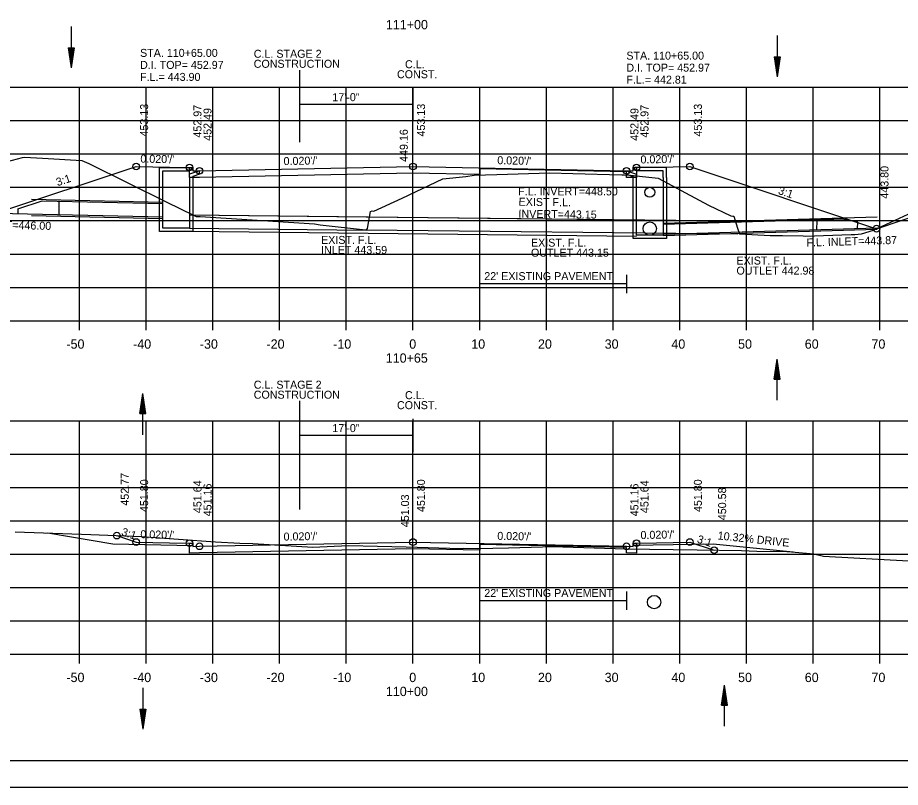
# Model space of a CAD drawing. Extents: x 1538688 to 1540766, y 656250 to 671912.
# Drawn here: x 1538798.9 to 1538931.2, y 657831.3 to 657946.7 of the extents above; entities that cross this region are included whole.
import ezdxf

# ---------------------------------------------------------------- set-up
doc = ezdxf.new("R2010")
doc.units = 0
for name, color, linetype in [('15', 7, 'Continuous'), ('16', 7, 'Continuous'), ('18', 7, 'Continuous'), ('20', 7, 'Continuous'), ('22', 7, 'Continuous'), ('26', 7, 'Continuous'), ('39', 7, 'Continuous'), ('40', 7, 'Continuous'), ('41', 7, 'Continuous'), ('42', 7, 'Continuous'), ('7', 7, 'Continuous'), ('Borings', 7, 'Continuous'), ('Default', 7, 'Continuous'), ('Horizontal Alignment', 7, 'Continuous'), ('RipRap', 7, 'Continuous'), ('Wall Heights', 7, 'Continuous')]:
    doc.layers.add(name, color=color, linetype=linetype)

msp = doc.modelspace()

# ---------------------------------------------------------------- linework, layer by layer
at = {"layer": '15'}
for p, q in [((1538806.47, 657942.19), (1538806.92, 657939.19)), ((1538806.47, 657942.19), (1538807.37, 657942.19)), ((1538806.55, 657942.19), (1538806.92, 657939.69)), ((1538806.62, 657942.19), (1538806.92, 657940.21)), ((1538806.7, 657942.19), (1538806.92, 657940.71)), ((1538806.78, 657942.19), (1538806.92, 657941.22)), ((1538806.85, 657942.19), (1538806.92, 657941.72)), ((1538807.37, 657942.19), (1538806.92, 657939.19)), ((1538807.07, 657942.19), (1538806.92, 657941.22)), ((1538807.22, 657942.19), (1538806.92, 657940.21)), ((1538807.3, 657942.19), (1538806.92, 657939.69)), ((1538807.14, 657942.19), (1538806.92, 657940.71)), ((1538806.99, 657942.19), (1538806.92, 657941.72)), ((1538912.35, 657940.82), (1538912.8, 657937.82)), ((1538912.35, 657940.82), (1538913.25, 657940.82)), ((1538912.43, 657940.82), (1538912.8, 657938.32)), ((1538912.5, 657940.82), (1538912.8, 657938.84)), ((1538912.58, 657940.82), (1538912.8, 657939.34)), ((1538912.66, 657940.82), (1538912.8, 657939.85)), ((1538912.73, 657940.82), (1538912.8, 657940.35)), ((1538913.25, 657940.82), (1538912.8, 657937.82)), ((1538912.95, 657940.82), (1538912.8, 657939.85)), ((1538913.1, 657940.82), (1538912.8, 657938.84)), ((1538913.18, 657940.82), (1538912.8, 657938.32)), ((1538913.03, 657940.82), (1538912.8, 657939.34)), ((1538912.87, 657940.82), (1538912.8, 657940.35)), ((1538912.35, 657892.5), (1538912.8, 657895.5)), ((1538912.43, 657892.5), (1538912.8, 657895)), ((1538912.5, 657892.5), (1538912.8, 657894.48)), ((1538913.25, 657892.5), (1538912.8, 657895.5)), ((1538913.18, 657892.5), (1538912.8, 657895)), ((1538913.1, 657892.5), (1538912.8, 657894.48)), ((1538912.58, 657892.5), (1538912.8, 657893.98)), ((1538912.66, 657892.5), (1538912.8, 657893.48)), ((1538912.73, 657892.5), (1538912.8, 657892.97)), ((1538913.03, 657892.5), (1538912.8, 657893.98)), ((1538912.95, 657892.5), (1538912.8, 657893.48)), ((1538912.87, 657892.5), (1538912.8, 657892.97)), ((1538912.35, 657892.5), (1538913.25, 657892.5)), ((1538817.23, 657887.33), (1538817.68, 657890.33)), ((1538818.13, 657887.33), (1538817.68, 657890.33)), ((1538817.3, 657887.33), (1538817.68, 657889.83)), ((1538817.38, 657887.33), (1538817.68, 657889.31)), ((1538818.05, 657887.33), (1538817.68, 657889.83)), ((1538817.98, 657887.33), (1538817.68, 657889.31)), ((1538817.45, 657887.33), (1538817.68, 657888.81)), ((1538817.53, 657887.33), (1538817.68, 657888.3)), ((1538817.61, 657887.33), (1538817.68, 657887.8)), ((1538817.9, 657887.33), (1538817.68, 657888.81)), ((1538817.83, 657887.33), (1538817.68, 657888.3)), ((1538817.75, 657887.33), (1538817.68, 657887.8)), ((1538817.23, 657887.33), (1538818.13, 657887.33)), ((1538904.41, 657843.61), (1538904.86, 657846.61)), ((1538905.31, 657843.61), (1538904.86, 657846.61)), ((1538904.49, 657843.61), (1538904.86, 657846.11)), ((1538904.56, 657843.61), (1538904.86, 657845.59)), ((1538905.24, 657843.61), (1538904.86, 657846.11)), ((1538905.16, 657843.61), (1538904.86, 657845.59)), ((1538904.64, 657843.61), (1538904.86, 657845.09)), ((1538904.71, 657843.61), (1538904.86, 657844.59)), ((1538904.79, 657843.61), (1538904.86, 657844.08)), ((1538905.08, 657843.61), (1538904.86, 657845.09)), ((1538905.01, 657843.61), (1538904.86, 657844.59)), ((1538904.93, 657843.61), (1538904.86, 657844.08)), ((1538817.23, 657842.99), (1538817.68, 657839.99)), ((1538817.23, 657842.99), (1538818.13, 657842.99)), ((1538817.3, 657842.99), (1538817.68, 657840.5)), ((1538817.38, 657842.99), (1538817.68, 657841.01)), ((1538817.45, 657842.99), (1538817.68, 657841.51)), ((1538817.53, 657842.99), (1538817.68, 657842.02)), ((1538817.61, 657842.99), (1538817.68, 657842.52)), ((1538818.13, 657842.99), (1538817.68, 657839.99)), ((1538817.83, 657842.99), (1538817.68, 657842.02)), ((1538817.98, 657842.99), (1538817.68, 657841.01)), ((1538818.05, 657842.99), (1538817.68, 657840.5)), ((1538817.9, 657842.99), (1538817.68, 657841.51)), ((1538817.75, 657842.99), (1538817.68, 657842.52)), ((1538904.41, 657843.61), (1538905.31, 657843.61))]:
    msp.add_line(p, q, dxfattribs=at)
at = {"layer": '16'}
for p, q in [((1538803.43, 657869.41), (1538813.18, 657867.79)), ((1538813.18, 657867.79), (1538825.18, 657867.55)), ((1538891.18, 657867.56), (1538903.18, 657867.8)), ((1538903.18, 657867.8), (1538915.19, 657866.56))]:
    msp.add_line(p, q, dxfattribs=at)
at = {"layer": '18'}
for points in [[(1538789.07, 657922.91), (1538799.63, 657925.71), (1538799.93, 657925.79), (1538802.65, 657925.64), (1538808.51, 657925.29), (1538809.57, 657924.8), (1538821.3, 657919.01), (1538825.29, 657917.06), (1538825.65, 657916.88), (1538826.25, 657916.85), (1538843.39, 657915.75), (1538844.28, 657915.6), (1538851.07, 657914.89), (1538851.25, 657914.93), (1538851.35, 657915.07), (1538851.8, 657917.61), (1538852.04, 657917.7), (1538852.29, 657917.68), (1538856.55, 657919.64), (1538862.64, 657922.51), (1538866.1, 657922.88), (1538867.33, 657923.07), (1538870.77, 657923.17), (1538878.68, 657923.42), (1538882.13, 657923.33), (1538889.5, 657923.13), (1538889.82, 657923.11), (1538890.78, 657923.06), (1538892.12, 657922.93), (1538894.95, 657922.6), (1538902.51, 657918.55), (1538905.84, 657916.96), (1538906.14, 657916.93), (1538906.27, 657916.9), (1538906.85, 657915.13), (1538907.13, 657914.29), (1538911.72, 657914.04), (1538913.57, 657914.03), (1538916.67, 657913.96), (1538917, 657913.92), (1538923.88, 657914.16), (1538924.44, 657914.18), (1538925.43, 657914.27), (1538927.22, 657914.85), (1538935.01, 657918.41)], [(1538798.55, 657869.6), (1538809.89, 657869.16), (1538817.47, 657868.87), (1538828.55, 657868.07), (1538832.24, 657867.89), (1538834.15, 657867.84), (1538843.18, 657867.26), (1538848.49, 657867.55), (1538852.84, 657867.45), (1538857.14, 657867.31), (1538865.34, 657867.08), (1538865.72, 657867.11), (1538867.8, 657867.09), (1538872.52, 657867.19), (1538879.3, 657867.39), (1538879.31, 657867.39), (1538880.67, 657867.34), (1538890.06, 657867.01), (1538900.8, 657866.87), (1538907.44, 657866.76), (1538909.71, 657866.69), (1538914.25, 657866.62), (1538914.91, 657866.58), (1538918.27, 657866.28), (1538919.72, 657865.91), (1538932.47, 657865.23)]]:
    msp.add_lwpolyline(points, dxfattribs=at)
at = {"layer": '20'}
for points in [[(1538784.23, 657921.03), (1538795.44, 657917.3), (1538816.67, 657924.37), (1538821.67, 657924.27), (1538824.67, 657924.21), (1538825.17, 657924.21), (1538825.18, 657923.71), (1538826.18, 657923.73), (1538858.18, 657924.37), (1538890.18, 657923.73), (1538891.18, 657923.71), (1538891.19, 657924.21), (1538891.69, 657924.21), (1538894.69, 657924.27), (1538899.69, 657924.37), (1538927.67, 657915.05), (1538938.79, 657918.76)], [(1538813.77, 657869.01), (1538816.67, 657868.05), (1538821.67, 657867.95), (1538824.67, 657867.89), (1538825.17, 657867.89), (1538825.18, 657867.39), (1538826.18, 657867.41), (1538858.18, 657868.05), (1538890.18, 657867.41), (1538891.18, 657867.39), (1538891.19, 657867.89), (1538891.69, 657867.89), (1538894.69, 657867.95), (1538899.69, 657868.05), (1538903.33, 657866.83)]]:
    msp.add_lwpolyline(points, dxfattribs=at)
at = {"layer": '22'}
for p, q in [((1538718.18, 657936.25), (1538998.18, 657936.25)), ((1538808.18, 657901.25), (1538808.18, 657936.25)), ((1538818.18, 657901.25), (1538818.18, 657936.25)), ((1538828.18, 657901.25), (1538828.18, 657936.25)), ((1538838.18, 657901.25), (1538838.18, 657936.25)), ((1538848.18, 657901.25), (1538848.18, 657936.25)), ((1538858.18, 657901.25), (1538858.18, 657936.25)), ((1538868.18, 657901.25), (1538868.18, 657936.25)), ((1538878.18, 657901.25), (1538878.18, 657936.25)), ((1538888.18, 657901.25), (1538888.18, 657936.25)), ((1538898.18, 657901.25), (1538898.18, 657936.25)), ((1538908.18, 657901.25), (1538908.18, 657936.25)), ((1538918.18, 657901.25), (1538918.18, 657936.25)), ((1538928.18, 657901.25), (1538928.18, 657936.25)), ((1538718.18, 657931.25), (1538998.18, 657931.25)), ((1538718.18, 657926.25), (1538998.18, 657926.25)), ((1538718.18, 657921.25), (1538998.18, 657921.25)), ((1538718.18, 657916.25), (1538998.18, 657916.25)), ((1538718.18, 657911.25), (1538998.18, 657911.25)), ((1538718.18, 657906.25), (1538998.18, 657906.25)), ((1538718.18, 657901.25), (1538998.18, 657901.25)), ((1538718.18, 657886.25), (1538998.18, 657886.25)), ((1538808.18, 657851.25), (1538808.18, 657886.25)), ((1538818.18, 657851.25), (1538818.18, 657886.25)), ((1538828.18, 657851.25), (1538828.18, 657886.25)), ((1538838.18, 657851.25), (1538838.18, 657886.25)), ((1538848.18, 657851.25), (1538848.18, 657886.25)), ((1538858.18, 657851.25), (1538858.18, 657886.25)), ((1538868.18, 657851.25), (1538868.18, 657886.25)), ((1538878.18, 657851.25), (1538878.18, 657886.25)), ((1538888.18, 657851.25), (1538888.18, 657886.25)), ((1538898.18, 657851.25), (1538898.18, 657886.25)), ((1538908.18, 657851.25), (1538908.18, 657886.25)), ((1538918.18, 657851.25), (1538918.18, 657886.25)), ((1538928.18, 657851.25), (1538928.18, 657886.25)), ((1538718.18, 657881.25), (1538998.18, 657881.25)), ((1538718.18, 657876.25), (1538998.18, 657876.25)), ((1538718.18, 657871.25), (1538998.18, 657871.25)), ((1538718.18, 657866.25), (1538998.18, 657866.25)), ((1538718.18, 657861.25), (1538998.18, 657861.25)), ((1538718.18, 657856.25), (1538998.18, 657856.25)), ((1538718.18, 657851.25), (1538998.18, 657851.25))]:
    msp.add_line(p, q, dxfattribs=at)
at = {"layer": '26'}
for p, q in [((1538801.01, 657919.45), (1538820.68, 657919)), ((1538801.01, 657917.04), (1538820.68, 657916.59)), ((1538824.68, 657917.11), (1538891.68, 657916.36)), ((1538927.76, 657916.78), (1538895.68, 657915.82)), ((1538824.68, 657914.7), (1538891.68, 657913.95)), ((1538927.76, 657914.95), (1538895.68, 657913.99)), ((1538687.78, 657831.27), (1539021.11, 657831.27))]:
    msp.add_line(p, q, dxfattribs=at)
msp.add_lwpolyline([(1538687.77, 658044.6), (1539021.11, 658044.6), (1539021.11, 657831.26), (1538687.77, 657831.26)], close=True, dxfattribs=at)
for centre in [(1538816.67, 657924.37), (1538824.67, 657924.21), (1538858.18, 657924.37), (1538891.69, 657924.21), (1538899.69, 657924.37), (1538826.18, 657923.73), (1538826.18, 657923.73), (1538890.18, 657923.73), (1538890.18, 657923.73), (1538927.67, 657915.05), (1538813.77, 657869.01), (1538816.67, 657868.05), (1538824.67, 657867.89), (1538826.18, 657867.41), (1538826.18, 657867.41), (1538858.18, 657868.05), (1538890.18, 657867.41), (1538890.18, 657867.41), (1538891.69, 657867.89), (1538899.69, 657868.05), (1538903.33, 657866.83)]:
    msp.add_circle(centre, 0.5, dxfattribs=at)
at = {"layer": '39'}
for p, q in [((1538806.92, 657945.38), (1538806.92, 657939.19)), ((1538912.8, 657944.01), (1538912.8, 657937.82)), ((1538820.18, 657924.21), (1538824.93, 657924.21)), ((1538820.18, 657922.71), (1538820.18, 657924.21)), ((1538820.68, 657922.71), (1538820.68, 657923.71)), ((1538820.68, 657923.71), (1538824.68, 657923.71)), ((1538825.01, 657924.05), (1538824.68, 657923.71)), ((1538826.18, 657923.73), (1538824.68, 657923.21)), ((1538825.01, 657924.05), (1538824.93, 657924.21)), ((1538890.18, 657923.73), (1538891.68, 657923.21)), ((1538891.34, 657924.05), (1538891.43, 657924.21)), ((1538891.34, 657924.05), (1538891.68, 657923.71)), ((1538896.18, 657924.21), (1538891.43, 657924.21)), ((1538895.68, 657923.71), (1538891.68, 657923.71)), ((1538895.68, 657922.71), (1538895.68, 657923.71)), ((1538896.18, 657922.71), (1538896.18, 657924.21)), ((1538824.68, 657922.71), (1538824.68, 657923.21)), ((1538826.18, 657923.2), (1538825.18, 657922.86)), ((1538825.18, 657922.71), (1538825.18, 657922.86)), ((1538890.18, 657923.2), (1538891.18, 657922.86)), ((1538891.18, 657922.71), (1538891.18, 657922.86)), ((1538891.68, 657922.71), (1538891.68, 657923.21)), ((1538805.07, 657919.21), (1538805.07, 657917.16)), ((1538795.66, 657917.37), (1538820.68, 657916.8)), ((1538798.94, 657918), (1538798.94, 657917.29)), ((1538824.67, 657917.13), (1538851.18, 657916.84)), ((1538851.17, 657916.84), (1538906.86, 657916.21)), ((1538922.55, 657916.46), (1538895.68, 657915.66)), ((1538824.67, 657915.13), (1538851.18, 657914.84)), ((1538906.87, 657914.23), (1538851.18, 657914.84)), ((1538927.76, 657915.11), (1538895.68, 657914.16)), ((1538912.8, 657889.31), (1538912.8, 657895.5)), ((1538817.68, 657884.14), (1538817.68, 657890.33)), ((1538904.86, 657840.42), (1538904.86, 657846.61)), ((1538817.68, 657846.18), (1538817.68, 657839.99))]:
    msp.add_line(p, q, dxfattribs=at)
for points in [[(1538826.18, 657923.2), (1538826.18, 657923.73)], [(1538890.18, 657923.2), (1538890.18, 657923.73)], [(1538825.18, 657922.71), (1538825.18, 657914.65), (1538822.68, 657914.65), (1538820.18, 657914.65), (1538820.18, 657922.71)], [(1538824.68, 657922.71), (1538824.68, 657915.15), (1538822.68, 657915.15), (1538820.68, 657915.15), (1538820.68, 657922.71)], [(1538896.18, 657922.71), (1538896.18, 657913.56), (1538893.68, 657913.56), (1538891.18, 657913.56), (1538891.18, 657922.71)], [(1538895.68, 657922.71), (1538895.68, 657914.06), (1538893.68, 657914.06), (1538891.68, 657914.06), (1538891.68, 657922.71)], [(1538798.94, 657918), (1538802.57, 657919.21), (1538820.68, 657918.8)], [(1538924.84, 657915.03), (1538924.85, 657916.03), (1538922.55, 657916.46), (1538918.72, 657916.34), (1538918.7, 657914.84)]]:
    msp.add_lwpolyline(points, dxfattribs=at)
for centre, radius in [((1538893.68, 657920.5), 0.75), ((1538893.68, 657915.06), 1), ((1538894.33, 657859.04), 1)]:
    msp.add_circle(centre, radius, dxfattribs=at)
at = {"layer": '7'}
for p, q in [((1538868.17, 657908.15), (1538868.17, 657905.4)), ((1538890.17, 657908.15), (1538890.17, 657905.4)), ((1538890.17, 657906.77), (1538868.17, 657906.77)), ((1538868.17, 657860.62), (1538868.17, 657857.87)), ((1538890.17, 657860.62), (1538890.17, 657857.87)), ((1538890.17, 657859.25), (1538868.17, 657859.25))]:
    msp.add_line(p, q, dxfattribs=at)
at = {"layer": 'Borings'}
for p, q in [((1538718.18, 657901.25), (1538998.18, 657901.25)), ((1538808.18, 657899.85), (1538808.18, 657901.25)), ((1538818.18, 657899.85), (1538818.18, 657901.25)), ((1538828.18, 657899.85), (1538828.18, 657901.25)), ((1538838.18, 657899.85), (1538838.18, 657901.25)), ((1538848.18, 657899.85), (1538848.18, 657901.25)), ((1538858.18, 657899.85), (1538858.18, 657901.25)), ((1538868.18, 657899.85), (1538868.18, 657901.25)), ((1538878.18, 657899.85), (1538878.18, 657901.25)), ((1538888.18, 657899.85), (1538888.18, 657901.25)), ((1538898.18, 657899.85), (1538898.18, 657901.25)), ((1538908.18, 657899.85), (1538908.18, 657901.25)), ((1538918.18, 657899.85), (1538918.18, 657901.25)), ((1538928.18, 657899.85), (1538928.18, 657901.25)), ((1538718.18, 657851.25), (1538998.18, 657851.25)), ((1538808.18, 657849.85), (1538808.18, 657851.25)), ((1538818.18, 657849.85), (1538818.18, 657851.25)), ((1538828.18, 657849.85), (1538828.18, 657851.25)), ((1538838.18, 657849.85), (1538838.18, 657851.25)), ((1538848.18, 657849.85), (1538848.18, 657851.25)), ((1538858.18, 657849.85), (1538858.18, 657851.25)), ((1538868.18, 657849.85), (1538868.18, 657851.25)), ((1538878.18, 657849.85), (1538878.18, 657851.25)), ((1538888.18, 657849.85), (1538888.18, 657851.25)), ((1538898.18, 657849.85), (1538898.18, 657851.25)), ((1538908.18, 657849.85), (1538908.18, 657851.25)), ((1538918.18, 657849.85), (1538918.18, 657851.25)), ((1538928.18, 657849.85), (1538928.18, 657851.25))]:
    msp.add_line(p, q, dxfattribs=at)
at = {"layer": 'Default'}
for p, q in [((1538841.17, 657938.84), (1538841.17, 657928.02)), ((1538858.18, 657936.17), (1538858.18, 657931.17)), ((1538858.18, 657933.67), (1538841.17, 657933.67)), ((1538841.17, 657889.21), (1538841.17, 657872.94)), ((1538858.18, 657886.53), (1538858.18, 657881.53)), ((1538858.18, 657884.03), (1538841.17, 657884.03))]:
    msp.add_line(p, q, dxfattribs=at)
at = {"layer": 'RipRap'}
msp.add_line((1539016.36, 657835.25), (1538700.18, 657835.25), dxfattribs=at)
at = {"layer": 'Wall Heights'}
for points in [[(1538891.69, 657924.21), (1538891.69, 657922.71), (1538890.18, 657922.73), (1538890.18, 657922.73), (1538890.18, 657923.57), (1538868.18, 657924.01), (1538868.18, 657923.17), (1538858.18, 657923.37), (1538826.18, 657922.73), (1538824.67, 657922.71), (1538824.67, 657924.21)], [(1538891.69, 657867.89), (1538891.69, 657866.39), (1538890.18, 657866.41), (1538890.18, 657866.41), (1538890.18, 657867.24), (1538868.18, 657867.68), (1538868.18, 657866.85), (1538858.18, 657867.05), (1538826.18, 657866.41), (1538824.67, 657866.39), (1538824.67, 657867.89)]]:
    msp.add_lwpolyline(points, dxfattribs=at)

# ---------------------------------------------------------------- texts
at = {"layer": '16'}
msp.add_text('10.32% DRIVE', height=1.2, rotation=354.1107, dxfattribs=at).set_placement((1538903.82, 657868.45))
at = {"layer": '40'}
for s, p in [('STA. 110+65.00', (1538817.26, 657940.81)), ('STA. 110+65.00', (1538890.17, 657940.4)), ('D.I. TOP= 452.97', (1538817.26, 657939.01)), ('D.I. TOP= 452.97', (1538890.17, 657938.6)), ('F.L.= 443.90', (1538817.26, 657937.21)), ('F.L.= 442.81', (1538890.17, 657936.8)), ('F.L. INVERT=448.50', (1538873.95, 657920.04)), ('EXIST. F.L.', (1538844.4, 657912.76)), ('EXIST. F.L.', (1538875.87, 657912.35)), ('INLET 443.59', (1538844.4, 657911.26)), ('OUTLET 443.15', (1538875.87, 657910.85)), ('EXIST. F.L.', (1538906.68, 657909.67)), ('OUTLET 442.98', (1538906.68, 657908.16))]:
    msp.add_text(s, height=1.2, dxfattribs=at).set_placement(p)
for s, rotation, p in [('EXIST F.L.', 359.3587, (1538874.01, 657918.49)), ('INVERT=443.15', 359.3587, (1538873.99, 657916.69)), ('F.L. INLET=446.00', 358.6892, (1538790.33, 657915.17)), ('F.L. INLET=443.87', 1.7075, (1538917.18, 657912.36))]:
    msp.add_text(s, height=1.2, rotation=rotation, dxfattribs=at).set_placement(p)
at = {"layer": '41'}
for s, p in [('453.13', (1538818.47, 657928.87)), ('452.97', (1538826.47, 657928.71)), ('452.49', (1538827.98, 657928.23)), ('453.13', (1538859.98, 657928.87)), ('452.49', (1538891.98, 657928.23)), ('452.97', (1538893.49, 657928.71)), ('453.13', (1538901.49, 657928.87)), ('449.16', (1538857.4, 657925.06)), ('443.80', (1538929.47, 657919.55)), ('452.77', (1538815.57, 657873.51)), ('451.80', (1538818.47, 657872.55)), ('451.64', (1538826.47, 657872.39)), ('451.80', (1538859.98, 657872.55)), ('451.64', (1538893.49, 657872.39)), ('451.80', (1538901.49, 657872.55)), ('451.16', (1538827.98, 657871.91)), ('451.16', (1538891.98, 657871.91)), ('450.58', (1538905.13, 657871.33)), ('451.03', (1538857.58, 657870.28))]:
    msp.add_text(s, height=1.2, rotation=90, dxfattribs=at).set_placement(p)
at = {"layer": '42'}
for s, rotation, p in [("0.020'/'", 358.8542, (1538817.3, 657924.96)), ("0.020'/'", 1.1458, (1538892.3, 657924.82)), ("0.020'/'", 1.1458, (1538838.79, 657924.58)), ("0.020'/'", 358.8542, (1538870.81, 657924.72)), ('3:1', 18.4349, (1538804.9, 657921.41)), ('3:1', 341.5651, (1538912.83, 657920.28)), ('3:1', 341.5651, (1538814.37, 657869.1)), ("0.020'/'", 358.8542, (1538817.3, 657868.63)), ("0.020'/'", 1.1458, (1538838.79, 657868.26)), ("0.020'/'", 358.8542, (1538870.81, 657868.39)), ("0.020'/'", 1.1458, (1538892.3, 657868.5)), ('3:1', 341.5651, (1538900.67, 657868.01))]:
    msp.add_text(s, height=1.2, rotation=rotation, dxfattribs=at).set_placement(p)
at = {"layer": '7'}
for p in [(1538868.87, 657907.33), (1538868.87, 657859.81)]:
    msp.add_text("22' EXISTING PAVEMENT", height=1.2, dxfattribs=at).set_placement(p)
at = {"layer": 'Default'}
for s, p in [('C.L. STAGE 2', (1538834.31, 657940.68)), ('CONSTRUCTION', (1538834.3, 657939.18)), ('C.L.', (1538856.98, 657939.11)), ('CONST.', (1538855.78, 657937.61)), ('17\'-0"', (1538846.09, 657934.17)), ('C.L. STAGE 2', (1538834.31, 657891.05)), ('CONSTRUCTION', (1538834.3, 657889.55)), ('C.L.', (1538856.98, 657889.48)), ('CONST.', (1538855.78, 657887.98)), ('17\'-0"', (1538846.09, 657884.54))]:
    msp.add_text(s, height=1.2, dxfattribs=at).set_placement(p)
at = {"layer": 'Horizontal Alignment'}
for s, p in [('111+00', (1538854.12, 657944.95)), ('-50', (1538806.22, 657897.05)), ('-40', (1538816.22, 657897.05)), ('-30', (1538826.22, 657897.05)), ('-20', (1538836.22, 657897.05)), ('-10', (1538846.22, 657897.05)), ('0', (1538857.62, 657897.05)), ('10', (1538866.92, 657897.05)), ('20', (1538876.92, 657897.05)), ('30', (1538886.92, 657897.05)), ('40', (1538896.92, 657897.05)), ('50', (1538906.92, 657897.05)), ('60', (1538916.92, 657897.05)), ('70', (1538926.92, 657897.05)), ('110+65', (1538854.1, 657894.95)), ('-50', (1538806.22, 657847.05)), ('-40', (1538816.22, 657847.05)), ('-30', (1538826.22, 657847.05)), ('-20', (1538836.22, 657847.05)), ('-10', (1538846.22, 657847.05)), ('0', (1538857.62, 657847.05)), ('10', (1538866.92, 657847.05)), ('20', (1538876.92, 657847.05)), ('30', (1538886.92, 657847.05)), ('40', (1538896.92, 657847.05)), ('50', (1538906.92, 657847.05)), ('60', (1538916.92, 657847.05)), ('70', (1538926.92, 657847.05)), ('110+00', (1538854.12, 657844.95))]:
    msp.add_text(s, height=1.4, dxfattribs=at).set_placement(p)

doc.saveas('drawing.dxf')
